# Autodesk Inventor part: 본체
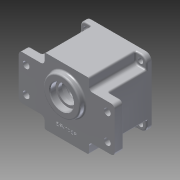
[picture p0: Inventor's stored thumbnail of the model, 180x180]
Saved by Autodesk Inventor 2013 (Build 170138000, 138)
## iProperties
Created: 2015-07
Part Number: 본체
Material: 알루미늄 6061
Document SubType Name: Modeling
Designer: user
Density: 2.71 g/cm^3
Mass: 700.948 g
Surface Area: 679.373 cm^2
Volume: 258.652 cm^3
Author: user
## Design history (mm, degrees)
sketch "스케치1"
  geometry: L1 (65, -30)-(65, 30); L2 (-65, 30)-(-65, -30); L3 (-30, 45)-(30, 45); L4 (30, -45)-(-30, -45); L5 (65, 30)-(35, 30); L6 (-35, 30)-(-65, 30); L7 (30, 45)-(30, 35); L8 (30, -35)-(30, -45); L9 (-30, -45)-(-30, -35); L10 (-30, 35)-(-30, 45); L11 (-65, -30)-(-35, -30); L12 (35, -30)-(65, -30); A1 r 5 centre (35, 35) between (30, 35) and (35, 30); A2 r 5 centre (35, -35) between (35, -30) and (30, -35); A3 r 5 centre (-35, -35) between (-30, -35) and (-35, -30); A4 r 5 centre (-35, 35) between (-35, 30) and (-30, 35); 5 further points
  constraints: 24 end point, 12 tangent, 10 parallel, 8 point on circle, 4 centre point, 4 perpendicular, 3 equal radius, 3 horizontal, 2 horizontal alignment, 2 midpoint, 2 vertical alignment
  dimensions: "d0" = 130 distance of L1.end L2.start; "d2" = 60 distance of L2.start L2.end; "d3" = 60 distance of L3.start L3.end; "d4" = 90 distance of L3.end L4.start; "d5" = 5 radius of A1; "d6" = 35 distance between parallel lines of L1 L8; "d7" = 75 distance between parallel lines of L5 L4; "d8" = 35 distance from line of point (30, 0) L1; "d9" = 60 distance from line of point (0, -30) L5
extrude "돌출1" new body sketch "스케치1" distance "d10" = 12; taper "d11" = 0 deg
sketch "스케치2"
  geometry: L1 (-45, -45)-(45, -45); L2 (45, -45)-(45, 45); L3 (45, 45)-(-45, 45); L4 (-45, 45)-(-45, -45); 3 further points
  constraints: 8 end point, 2 midpoint, 2 parallel, 1 horizontal, 1 horizontal alignment, 1 perpendicular, 1 vertical alignment
  dimensions: "d12" = 90 distance of L3.end L2.end; "d13" = 90 distance of L2.end L1.end
extrude "돌출2" join sketch "스케치2" distance "d14" = 58; taper "d15" = 0 deg
sketch "스케치3"
  geometry: L1 (35, 30)-(45, 30) reference; L2 (45, 45)-(45, 30) reference; L3 (35, 30)-(45, 30) reference; L4 (30, 45)-(30, 35) reference; L5 (-30, 45)-(30, 45) reference; L6 (-30, 35)-(-30, 45) reference; L7 (-45, 30)-(-35, 30) reference; L8 (-45, -30)-(-45, 30) reference; L9 (-45, -30)-(-65, -30) reference; L10 (-65, -30)-(-65, 30) reference; L11 (-65, 30)-(-45, 30) reference; L12 (-45, 30)-(-45, 45) reference; L13 (-45, 45)-(-30, 45) reference; L14 (30, 45)-(45, 45) reference; L15 (45, 30)-(45, -30) reference; L16 (65, -30)-(45, -30) reference; L17 (65, 30)-(65, -30) reference; L18 (45, 30)-(65, 30) reference; L19 (-45, -45)-(-45, -30) reference; L20 (-35, -30)-(-45, -30) reference; L21 (-30, -45)-(-30, -35) reference; L22 (-30, -45)-(-45, -45) reference; L23 (45, -30)-(45, -45) reference; L24 (45, -45)-(30, -45) reference; L25 (30, -45)-(-30, -45) reference; L26 (45, -30)-(35, -30) reference; L27 (30, -35)-(30, -45) reference; A1 r 5 centre (35, 35) between (30, 35) and (35, 30) reference; A2 r 5 centre (-35, 35) between (-35, 30) and (-30, 35) reference; A3 r 5 centre (-35, -35) between (-30, -35) and (-35, -30) reference; A4 r 5 centre (35, -35) between (35, -30) and (30, -35) reference; 1 further point
extrude "돌출3" cut sketch "스케치3" distance "d16" = 51; taper "d17" = 0 deg
sketch "스케치4"
  geometry: L1 (60, 0)-(60, 63) reference; L2 (60, 63)-(75, 63) reference; L3 (75, 63)-(75, 70) reference; L4 (-15, 70)-(75, 70) reference; L5 (-15, 63)-(-15, 70) reference; L6 (-15, 63)-(0, 63) reference; L7 (0, 0)-(0, 63) reference; L8 (60, 0)-(0, 0) reference; 1 further point
fillet "모깎기1" dims "d18" = 8
fillet "모깎기2" dims "d19" = 5
sketch "스케치5"
  geometry: L1 (65, -25)-(65, 25) reference; L2 (60, 30)-(35, 30) reference; C1 r 4.5 at (55, 17.5); C2 r 4.5 at (-55, 17.5); C3 r 4.5 at (55, -17.5); C4 r 4.5 at (-55, -17.5); 1 further point
  constraints: 4 centre point, 3 equal radius
  dimensions: "d26" = 9 diameter of C1; "d27" = 10 distance from line of C1.centre L1; "d28" = 12.5 distance from line of C1.centre L2; "d29" = 10 distance from line of C3.centre L1; "d30" = 47.5 distance from line of C3.centre L2; "d31" = 120 distance from line of C2.centre L1; "d32" = 12.5 distance from line of C2.centre L2; "d33" = 120 distance from line of C4.centre L1; "d34" = 47.5 distance from line of C4.centre L2
extrude "돌출4" cut sketch "스케치5" stored distance "d35" = 51; taper "d36" = 0 deg
sketch "스케치6"
  geometry: L1 (-30, -35)-(-30, -45) reference; L2 (0, 0)-(0, 11); C1 r 25 at (0, 11); 1 further point
  constraints: 2 end point, 1 centre point, 1 coincident, 1 parallel
  dimensions: "d37" = 11 distance of L2.start L2.end; "d38" = 50 diameter of C1
extrude "돌출5" join sketch "스케치6" distance "d39" = 7; taper "d40" = 0 deg
fillet "모깎기4" dims "d41" = 2
sketch "스케치7"
  geometry: C1 r 23 at (0, 0) reference; 1 further point
hole "구멍1" sketch "스케치7" at (0, 0) diameter "d42" = 25; stored, may be unused: countersink angle "d46" = 90 deg, drill point angle "d48" = 118 deg; dims "d43" = 6, "d44" = 32, "d45" = 8, "d47" = 8
chamfer "모따기1" distance "d49" = 1; stored, may be unused: second distance "d50" = 2, angle "d51" = 45 deg
fillet "모깎기5" dims "d52" = 0.3
fillet "모깎기8" dims "d55" = 2
sketch "스케치8"
  geometry: C1 r 3.5 at (-37, -37); C2 r 3.5 at (37, -37); C3 r 3.5 at (37, 37); C4 r 3.5 at (-37, 37); A1 r 8 centre (-37, 37) between (-37, 45) and (-45, 37) reference; A2 r 8 centre (-37, -37) between (-45, -37) and (-37, -45) reference; A3 r 8 centre (37, -37) between (37, -45) and (45, -37) reference; A4 r 8 centre (37, 37) between (45, 37) and (37, 45) reference; 1 further point
  constraints: 4 centre point, 3 concentric, 2 equal radius, 1 coincident
  dimensions: "d65" = 7 diameter of C1; "d66" = 7 diameter of C2
extrude "돌출6" cut sketch "스케치8" stored distance "d67" = 7; taper "d68" = 0 deg
sketch "스케치9"
  geometry: C1 r 12.5 at (0, -11) reference; C2 r 40 at (0, 0); 1 further point
  constraints: 1 centre point, 1 coincident
  dimensions: "d69" = 80 diameter of C2
extrude "돌출7" cut sketch "스케치9" distance "d70" = 9; taper "d71" = 0 deg
sketch "스케치10"
  geometry: C1 r 12.5 at (0, -11) reference; C2 r 40 at (0, 0) reference; C3 r 39 at (0, 0)
  constraints: 1 centre point, 1 coincident
  dimensions: "d72" = 78 diameter of C3
extrude "돌출8" cut sketch "스케치10" distance "d73" = 52; taper "d74" = 0 deg
node "작업 평면1"
sketch "스케치11"
  geometry: 1 further point
sketch "스케치12"
  geometry: L1 (0, 0)-(-55.97, -55.97); L2 (0, 0)-(-45, 0); L3 (-30, -45)-(-30, -35) reference; L4 (-35, -30)-(-45, -30) reference; L5 (-45, -30)-(-45, 30) reference; L6 (-45, 30)-(-35, 30) reference; L7 (-30, 35)-(-30, 45) reference; L8 (30, -45)-(-30, -45) reference; L9 (-30, 45)-(30, 45) reference; L10 (30, 45)-(30, 35) reference; L11 (30, -35)-(30, -45) reference; L12 (35, 30)-(45, 30) reference; L13 (45, 30)-(45, -30) reference; L14 (45, -30)-(35, -30) reference; C1 r 39 at (0, 0) reference; C2 r 40 at (0, 0) reference; C3 r 39 at (0, 0) reference; C4 r 40 at (0, 0) reference; C5 r 4 at (24.749, -24.749); C6 r 4 at (24.749, 24.749); C7 r 4 at (-24.749, 24.749); A1 r 4 centre (-24.749, -24.749) between (-21.809, -27.462) and (-27.462, -21.809); A2 r 39 centre (0, 0) between (-21.134, -32.777) and (-32.777, -21.134); A3 r 3.5 centre (-19.238, -29.836) between (-21.809, -27.462) and (-21.134, -32.777); A4 r 3.5 centre (-29.836, -19.238) between (-32.777, -21.134) and (-27.462, -21.809); A5 r 5 centre (-35, -35) between (-30, -35) and (-35, -30) reference; A6 r 5 centre (-35, 35) between (-35, 30) and (-30, 35) reference; A7 r 5 centre (35, 35) between (30, 35) and (35, 30) reference; A8 r 5 centre (35, -35) between (35, -30) and (30, -35) reference
  constraints: 8 point on circle, 7 centre point, 5 tangent, 4 end point, 1 coincident, 1 point on line, 9 other
  dimensions: "d75" = 45 deg angle of L2 L1; "d77" = 8 diameter of A1; "d80" = 360 deg dimension on C1.centre A1.centre (derived); "d83" = 49.49747 distance of C5.centre C6.centre; "d85" = 7 diameter of A3; "d87" = 7 diameter of A4
extrude "돌출9" join sketch "스케치12" stored distance "d88" = 52; taper "d89" = 0 deg
sketch "스케치13"
  geometry: A1 r 4 centre (-24.749, -24.749) between (-21.809, -27.462) and (-27.462, -21.809) reference; A2 r 4 centre (-24.749, 24.749) between (-27.462, 21.809) and (-21.809, 27.462) reference; A3 r 4 centre (24.749, 24.749) between (21.809, 27.462) and (27.462, 21.809) reference; A4 r 4 centre (24.749, -24.749) between (27.462, -21.809) and (21.809, -27.462) reference
hole "구멍2" sketch "스케치13" at (24.749, 24.749), (24.749, -24.749), (-24.749, -24.749), (-24.749, 24.749) diameter "d93" = 3.459; stored, may be unused: countersink angle "d97" = 90 deg, drill point angle "d99" = 118 deg; dims "d94" = 12, "d95" = 32, "d96" = 8, "d98" = 15
sketch "스케치14"
  geometry: L1 (-60, 30)-(-35, 30) reference; L2 (-30, 35)-(-30, 45) reference; L3 (30, 45)-(30, 35) reference; L4 (35, 30)-(60, 30) reference; L5 (65, 25)-(65, -25) reference; L6 (60, -30)-(35, -30) reference; L7 (30, -35)-(30, -45) reference; L8 (-30, -45)-(-30, -35) reference; L9 (-35, -30)-(-60, -30) reference; L10 (-65, -25)-(-65, 25) reference; L11 (30, -45)-(-30, -45) reference; L12 (-30, 45)-(30, 45) reference; C1 r 12.5 at (0, -11) reference; C2 r 12.5 at (0, -11) reference; C3 r 4.5 at (55, 17.5) reference; C4 r 4.5 at (55, -17.5) reference; C5 r 4.5 at (-55, -17.5) reference; C6 r 4.5 at (-55, 17.5) reference; C7 r 20.5 at (0, -11); A1 r 4 centre (-24.749, -24.749) between (-21.809, -27.462) and (-27.462, -21.809) reference; A2 r 3.5 centre (-19.238, -29.836) between (-21.809, -27.462) and (-21.134, -32.777) reference; A3 r 39 centre (0, 0) between (-21.134, -32.777) and (21.134, -32.777) reference; A4 r 3.5 centre (19.238, -29.836) between (21.134, -32.777) and (21.809, -27.462) reference; A5 r 4 centre (24.749, -24.749) between (27.462, -21.809) and (21.809, -27.462) reference; A6 r 3.5 centre (29.836, -19.238) between (27.462, -21.809) and (32.777, -21.134) reference; A7 r 39 centre (0, 0) between (32.777, -21.134) and (32.777, 21.134) reference; A8 r 3.5 centre (29.836, 19.238) between (32.777, 21.134) and (27.462, 21.809) reference; A9 r 4 centre (24.749, 24.749) between (21.809, 27.462) and (27.462, 21.809) reference; A10 r 3.5 centre (19.238, 29.836) between (21.809, 27.462) and (21.134, 32.777) reference; A11 r 39 centre (0, 0) between (21.134, 32.777) and (-21.134, 32.777) reference; A12 r 3.5 centre (-19.238, 29.836) between (-21.134, 32.777) and (-21.809, 27.462) reference; A13 r 4 centre (-24.749, 24.749) between (-27.462, 21.809) and (-21.809, 27.462) reference; A14 r 3.5 centre (-29.836, 19.238) between (-27.462, 21.809) and (-32.777, 21.134) reference; A15 r 39 centre (0, 0) between (-32.777, 21.134) and (-32.777, -21.134) reference; A16 r 3.5 centre (-29.836, -19.238) between (-32.777, -21.134) and (-27.462, -21.809) reference; A17 r 5 centre (-60, 25) between (-60, 30) and (-65, 25) reference; A18 r 5 centre (-35, 35) between (-35, 30) and (-30, 35) reference; A19 r 5 centre (35, 35) between (30, 35) and (35, 30) reference; A20 r 5 centre (60, 25) between (65, 25) and (60, 30) reference; A21 r 5 centre (60, -25) between (60, -30) and (65, -25) reference; A22 r 5 centre (35, -35) between (35, -30) and (30, -35) reference; A23 r 5 centre (-35, -35) between (-30, -35) and (-35, -30) reference; A24 r 5 centre (-60, -25) between (-65, -25) and (-60, -30) reference
  constraints: 1 centre point, 1 coincident
  dimensions: "d100" = 41 diameter of C7
extrude "돌출10" join sketch "스케치14" distance "d101" = 7; taper "d102" = 0 deg
sketch "스케치15"
  geometry: L1 (-60, 30)-(-35, 30) reference; L2 (-30, 35)-(-30, 45) reference; L3 (30, 45)-(30, 35) reference; L4 (35, 30)-(60, 30) reference; L5 (65, 25)-(65, -25) reference; L6 (60, -30)-(35, -30) reference; L7 (30, -35)-(30, -45) reference; L8 (-30, -45)-(-30, -35) reference; L9 (-35, -30)-(-60, -30) reference; L10 (-65, -25)-(-65, 25) reference; L11 (0, 0)-(0, 20); L12 (30, -45)-(-30, -45) reference; L13 (-30, 45)-(30, 45) reference; C1 r 20.5 at (0, -11) reference; C2 r 12.5 at (0, -11) reference; C3 r 4.5 at (55, 17.5) reference; C4 r 4.5 at (55, -17.5) reference; C5 r 4.5 at (-55, -17.5) reference; C6 r 4.5 at (-55, 17.5) reference; C7 r 14 at (0, 20); A1 r 4 centre (-24.749, -24.749) between (-21.809, -27.462) and (-27.462, -21.809) reference; A2 r 3.5 centre (-19.238, -29.836) between (-21.809, -27.462) and (-21.134, -32.777) reference; A3 r 39 centre (0, 0) between (-21.134, -32.777) and (21.134, -32.777) reference; A4 r 3.5 centre (19.238, -29.836) between (21.134, -32.777) and (21.809, -27.462) reference; A5 r 4 centre (24.749, -24.749) between (27.462, -21.809) and (21.809, -27.462) reference; A6 r 3.5 centre (29.836, -19.238) between (27.462, -21.809) and (32.777, -21.134) reference; A7 r 39 centre (0, 0) between (32.777, -21.134) and (32.777, 21.134) reference; A8 r 3.5 centre (29.836, 19.238) between (32.777, 21.134) and (27.462, 21.809) reference; A9 r 4 centre (24.749, 24.749) between (21.809, 27.462) and (27.462, 21.809) reference; A10 r 3.5 centre (19.238, 29.836) between (21.809, 27.462) and (21.134, 32.777) reference; A11 r 39 centre (0, 0) between (21.134, 32.777) and (-21.134, 32.777) reference; A12 r 3.5 centre (-19.238, 29.836) between (-21.134, 32.777) and (-21.809, 27.462) reference; A13 r 4 centre (-24.749, 24.749) between (-27.462, 21.809) and (-21.809, 27.462) reference; A14 r 3.5 centre (-29.836, 19.238) between (-27.462, 21.809) and (-32.777, 21.134) reference; A15 r 39 centre (0, 0) between (-32.777, 21.134) and (-32.777, -21.134) reference; A16 r 3.5 centre (-29.836, -19.238) between (-32.777, -21.134) and (-27.462, -21.809) reference; A17 r 5 centre (-60, 25) between (-60, 30) and (-65, 25) reference; A18 r 5 centre (-35, 35) between (-35, 30) and (-30, 35) reference; A19 r 5 centre (35, 35) between (30, 35) and (35, 30) reference; A20 r 5 centre (60, 25) between (65, 25) and (60, 30) reference; A21 r 5 centre (60, -25) between (60, -30) and (65, -25) reference; A22 r 5 centre (35, -35) between (35, -30) and (30, -35) reference; A23 r 5 centre (-35, -35) between (-30, -35) and (-35, -30) reference; A24 r 5 centre (-60, -25) between (-65, -25) and (-60, -30) reference
  constraints: 2 end point, 1 centre point, 1 coincident, 1 parallel
  dimensions: "d103" = 20 distance of L11.start L11.end; "d104" = 28 diameter of C7
extrude "돌출11" join sketch "스케치15" distance "d105" = 7; taper "d106" = 0 deg
fillet "모깎기9" dims "d107" = 3
fillet "모깎기10" dims "d108" = 2
fillet "모깎기11" dims "d109" = 2
sketch "스케치16"
  geometry: C1 r 12.5 at (0, -11) reference; A1 r 20.5 centre (0, -11) between (-11.115, 6.225) and (11.115, 6.225) reference; A2 r 3 centre (12.742, 8.746) between (10.493, 10.732) and (11.115, 6.225) reference; A3 r 14 centre (0, 20) between (10.493, 10.732) and (-10.493, 10.732) reference; A4 r 3 centre (-12.742, 8.746) between (-11.115, 6.225) and (-10.493, 10.732) reference; 1 further point
sketch "스케치17"
  geometry: A1 r 20.5 centre (0, -11) between (-11.115, 6.225) and (11.115, 6.225) reference; 1 further point
hole "구멍3" sketch "스케치17" at (0, -11) diameter "d110" = 25; stored, may be unused: countersink angle "d114" = 90 deg, drill point angle "d116" = 118 deg; dims "d111" = 6, "d112" = 35, "d113" = 10, "d115" = 8
fillet "모깎기12" dims "d117" = 0.3
chamfer "모따기2" distance "d118" = 1; stored, may be unused: second distance "d119" = 2, angle "d120" = 45 deg
sketch "스케치18"
  geometry: A1 r 14 centre (0, 20) between (10.493, 10.732) and (-10.493, 10.732) reference; 1 further point
hole "구멍4" sketch "스케치18" at (0, 20) diameter "d121" = 22; stored, may be unused: countersink angle "d125" = 90 deg, drill point angle "d127" = 0 deg; dims "d122" = 6, "d123" = 35, "d124" = 10, "d126" = 7
sketch "스케치19"
  geometry: C1 r 11 at (0, 0) reference; 1 further point
hole "구멍5" sketch "스케치19" at (0, 0) diameter "d128" = 19; stored, may be unused: countersink angle "d132" = 90 deg, drill point angle "d134" = 0 deg; dims "d129" = 6, "d130" = 35, "d131" = 10, "d133" = 1
fillet "모깎기13" dims "d135" = 1
sketch "스케치20"
  geometry: 1 further point
chamfer "모따기3" distance "d136" = 1; stored, may be unused: second distance "d137" = 2, angle "d138" = 45 deg
sketch "스케치21"
  geometry: L1 (-30, -45)-(30, -45) reference; L2 (-30, -35)-(-30, -45) reference; L3 (0, -45)-(0, -30); 5 further points
  constraints: 2 end point, 1 coincident, 1 midpoint, 1 parallel, 1 other
  dimensions: "d139" = 15 distance of L3.start L3.end
feature "엠보싱1" sketch "스케치21" dims "d0" = 130, "d2" = 60, "d3" = 60, "d4" = 90, "d5" = 5, "d6" = 35, "d7" = 75, "d8" = 35, "d9" = 60, "d140" = 0.5, "d141" = 0
sketch "스케치22"
  geometry: C1 r 1.73 at (-24.749, -24.749) reference; C2 r 1.73 at (24.749, 24.749) reference; C3 r 1.73 at (24.749, -24.749) reference; C4 r 1.73 at (-24.749, 24.749) reference; C5 r 40 at (0, 0) reference; A1 r 3.5 centre (-19.238, -29.836) between (-21.809, -27.462) and (-21.134, -32.777) reference; A2 r 4 centre (-24.749, -24.749) between (-21.809, -27.462) and (-27.462, -21.809) reference; A3 r 3.5 centre (-29.836, -19.238) between (-32.777, -21.134) and (-27.462, -21.809) reference; A4 r 39 centre (0, 0) between (-32.777, 21.134) and (-32.777, -21.134) reference; A5 r 3.5 centre (-29.836, 19.238) between (-27.462, 21.809) and (-32.777, 21.134) reference; A6 r 4 centre (-24.749, 24.749) between (-27.462, 21.809) and (-21.809, 27.462) reference; A7 r 3.5 centre (-19.238, 29.836) between (-21.134, 32.777) and (-21.809, 27.462) reference; A8 r 39 centre (0, 0) between (21.134, 32.777) and (-21.134, 32.777) reference; A9 r 3.5 centre (19.238, 29.836) between (21.809, 27.462) and (21.134, 32.777) reference; A10 r 4 centre (24.749, 24.749) between (21.809, 27.462) and (27.462, 21.809) reference; A11 r 3.5 centre (29.836, 19.238) between (32.777, 21.134) and (27.462, 21.809) reference; A12 r 39 centre (0, 0) between (32.777, -21.134) and (32.777, 21.134) reference; A13 r 3.5 centre (29.836, -19.238) between (27.462, -21.809) and (32.777, -21.134) reference; A14 r 4 centre (24.749, -24.749) between (27.462, -21.809) and (21.809, -27.462) reference; A15 r 3.5 centre (19.238, -29.836) between (21.134, -32.777) and (21.809, -27.462) reference; A16 r 39 centre (0, 0) between (-21.134, -32.777) and (21.134, -32.777) reference
fillet "모깎기16" dims "d144" = 2
fillet "모깎기17" dims "d145" = 2
fillet "모깎기18" dims "d146" = 2
fillet "모깎기19" dims "d147" = 2
fillet "모깎기20" dims "d148" = 2
fillet "모깎기21" dims "d149" = 2
fillet "모깎기22" dims "d150" = 2
fillet "모깎기23" dims "d151" = 2
fillet "모깎기24" dims "d152" = 2
node "솔리드1"
pattern_circular "원형 패턴1" dims angle "d91" = 360 deg
node "절단 모서리 투영1"
node "절단 모서리 투영2"
node "절단 모서리 투영3"
node "절단 모서리 투영4"
